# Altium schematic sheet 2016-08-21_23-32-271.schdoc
size 406 x 220 mm; SheetNumber: 1; SheetTotal: 1
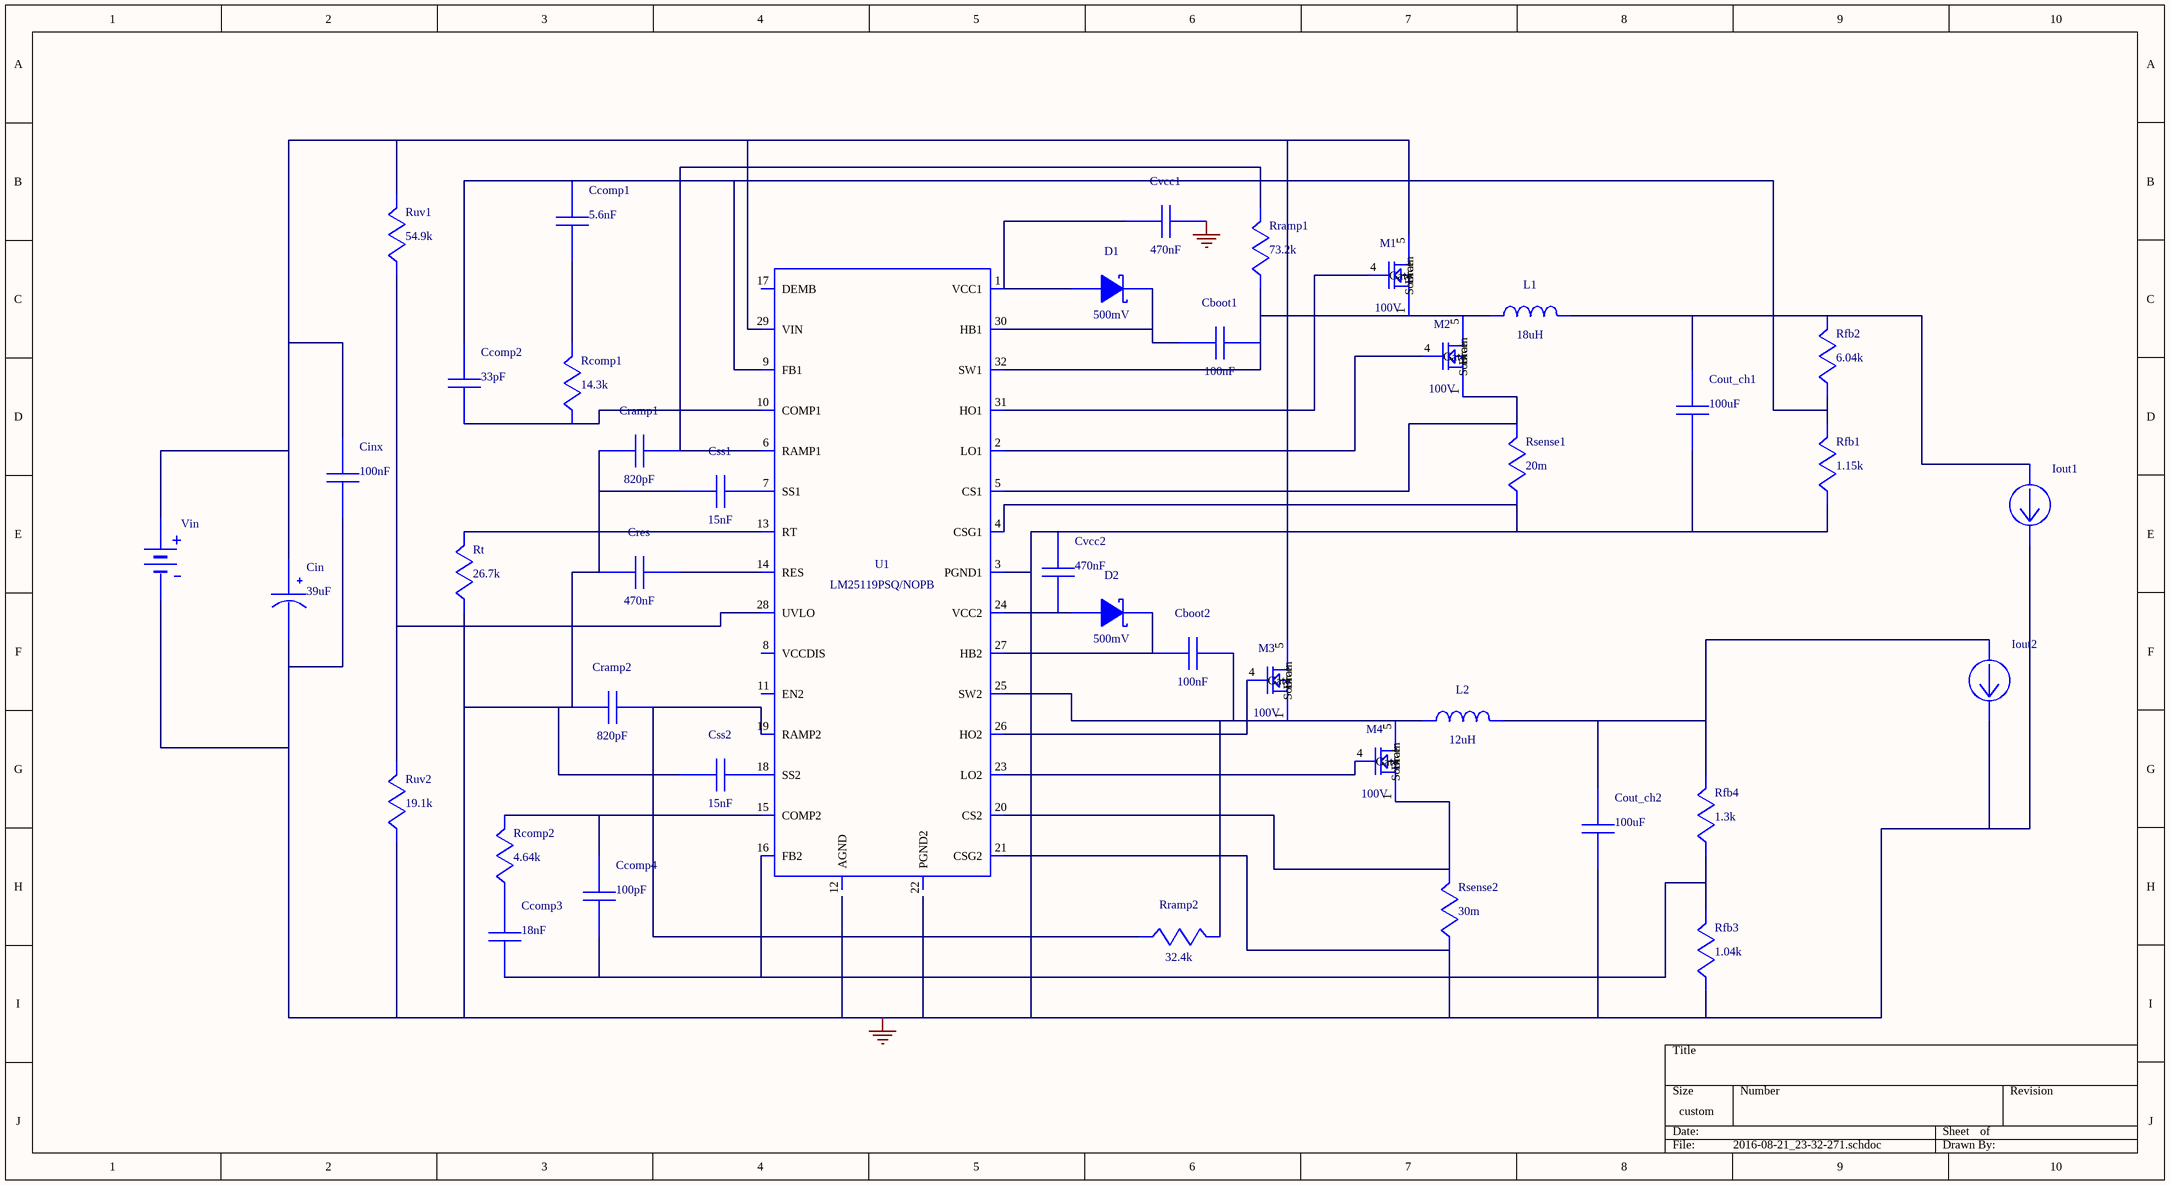
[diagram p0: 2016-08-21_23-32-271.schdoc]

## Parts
Cboot1  value 100nF  (hidden comment: GRM155R61A104KA01D)
Cboot2  value 100nF  (hidden comment: GRM155R61A104KA01D)
Ccomp1  value 5.6nF  (hidden comment: CC0805KRX7R9BB562)
Ccomp2  value 33pF  (hidden comment: C0805C330K5GACTU)
Ccomp3  value 18nF  (hidden comment: CC0805KRX7R9BB183)
Ccomp4  value 100pF  (hidden comment: CC0805JRNPO9BN101)
Cin  value 39uF  (hidden comment: GENERIC_CAP_POLARIZED)
Cinx  value 100nF  (hidden comment: C0805C104K5RACTU)
Cout_ch1  value 100uF  (hidden comment: GRM31CR60J107ME39L)
Cout_ch2  value 100uF  (hidden comment: GRM31CD80G107ME39L)
Cramp1  value 820pF  (hidden comment: CC0805KRX7R9BB821)
Cramp2  value 820pF  (hidden comment: CC0805KRX7R9BB821)
Cres  value 470nF  (hidden comment: GRM155C80J474KE19D)
Css1  value 15nF  (hidden comment: CC0805KRX7R9BB153)
Css2  value 15nF  (hidden comment: CC0805KRX7R9BB153)
Cvcc1  value 470nF  (hidden comment: GRM155R61A474KE15D)
Cvcc2  value 470nF  (hidden comment: GRM155R61A474KE15D)
D1  value 500mV  (hidden comment: SS14-E3/61T)
D2  value 500mV  (hidden comment: SS14-E3/61T)
Iout1  WB_CURRENT_LOAD  (value not drawn)
Iout2  WB_CURRENT_LOAD  (value not drawn)
L1  value 18uH  (hidden comment: SRR1280-180M)
L2  value 12uH  (hidden comment: SRR1206-120ML)
M1  value 100V  (hidden comment: CSD19537Q3)
M2  value 100V  (hidden comment: CSD19537Q3)
M3  value 100V  (hidden comment: CSD19537Q3)
M4  value 100V  (hidden comment: CSD19537Q3)
Rcomp1  value 14.3k  (hidden comment: CRCW040214K3FKED)
Rcomp2  value 4.64k  (hidden comment: CRCW04024K64FKED)
Rfb1  value 1.15k  (hidden comment: CRCW04021K15FKED)
Rfb2  value 6.04k  (hidden comment: CRCW04026K04FKED)
Rfb3  value 1.04k  (hidden comment: RT0805BRD071K04L)
Rfb4  value 1.3k  (hidden comment: CRCW04021K30FKED)
Rramp1  value 73.2k  (hidden comment: CRCW040273K2FKED)
Rramp2  value 32.4k  (hidden comment: CRCW040232K4FKED)
Rsense1  value 20m  (hidden comment: CSR1206FK20L0)
Rsense2  value 30m  (hidden comment: CSR1206FK30L0)
Rt  value 26.7k  (hidden comment: CRCW040226K7FKED)
Ruv1  value 54.9k  (hidden comment: CRCW040254K9FKED)
Ruv2  value 19.1k  (hidden comment: CRCW040219K1FKED)
U1  LM25119PSQ/NOPB
Vin  WB_BATTERY  (value not drawn)

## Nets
0: Cin.2(-) Cinx.2 Cout_ch1.2 Cout_ch2.2 Cramp1.2 Cramp2.2 Cres.2 Css1.2 Css2.2 Cvcc1.2 Cvcc2.2 Iout1.2(-) Iout2.2(-) Rfb1.2 Rfb3.2 Rsense1.2 Rsense2.2 Rt.2 Ruv2.2 U1.3(PGND1) U1.4(CSG1) U1.21(CSG2) U1.33(EP) Vin.2(-)
NetCboot1_1: Cboot1.1 L1.1 M1.1(Source) M1.2(Source) M1.3(Source) M2.5(Drain) M2.6(Drain) M2.7(Drain) M2.8(Drain) M2.9(Drain) Rramp1.2 U1.32(SW1)
NetCboot1_2: Cboot1.2 D1.1(K) U1.30(HB1)
NetCboot2_1: Cboot2.1 L2.1 M3.1(Source) M3.2(Source) M3.3(Source) M4.5(Drain) M4.6(Drain) M4.7(Drain) M4.8(Drain) M4.9(Drain) Rramp2.1 U1.25(SW2)
NetCboot2_2: Cboot2.2 D2.1(K) U1.27(HB2)
NetCcomp1_1: Ccomp1.1 Rcomp1.1
NetCcomp1_2: Ccomp1.2 Ccomp2.2 Rfb1.1 Rfb2.2 U1.9(FB1)
NetCcomp2_1: Ccomp2.1 Rcomp1.2 U1.10(COMP1)
NetCcomp3_1: Ccomp3.1 Rcomp2.2
NetCcomp3_2: Ccomp3.2 Ccomp4.2 Rfb3.1 Rfb4.2 U1.16(FB2)
NetCcomp4_1: Ccomp4.1 Rcomp2.1 U1.15(COMP2)
NetCin_1: Cin.1(+) Cinx.1 M1.5(Drain) M1.6(Drain) M1.7(Drain) M1.8(Drain) M1.9(Drain) M3.5(Drain) M3.6(Drain) M3.7(Drain) M3.8(Drain) M3.9(Drain) Ruv1.1 U1.29(VIN) Vin.1(+)
NetCout_ch1_1: Cout_ch1.1 Iout1.1(+) L1.2 Rfb2.1
NetCout_ch2_1: Cout_ch2.1 Iout2.1(+) L2.2 Rfb4.1
NetCramp1_1: Cramp1.1 Rramp1.1 U1.6(RAMP1)
NetCramp2_1: Cramp2.1 Rramp2.2 U1.19(RAMP2)
NetCres_1: Cres.1 U1.14(RES)
NetCss1_1: Css1.1 U1.7(SS1)
NetCss2_1: Css2.1 U1.18(SS2)
NetCvcc1_1: Cvcc1.1 D1.2(A) U1.1(VCC1)
NetCvcc2_1: Cvcc2.1 D2.2(A) U1.24(VCC2)
NetM1_4: M1.4(Gate) U1.31(HO1)
NetM2_1: M2.1(Source) M2.2(Source) M2.3(Source) Rsense1.1 U1.5(CS1)
NetM2_4: M2.4(Gate) U1.2(LO1)
NetM3_4: M3.4(Gate) U1.26(HO2)
NetM4_1: M4.1(Source) M4.2(Source) M4.3(Source) Rsense2.1 U1.20(CS2)
NetM4_4: M4.4(Gate) U1.23(LO2)
NetRt_1: Rt.1 U1.13(RT)
NetRuv1_2: Ruv1.2 Ruv2.1 U1.28(UVLO)

Not connected (* = marked no-connect by the designer): U1 8(VCCDIS) 11(EN2) 12(AGND) 17(DEMB) 22(PGND2)

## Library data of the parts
Cboot1 Cboot2 = GRM155R61A104KA01D: GRM155R61A104KA0; Manufacturer Name: MuRata
Ccomp1 = CC0805KRX7R9BB562: CC0805KRX7R9BB56; Manufacturer Name: Yageo America
Ccomp2 = C0805C330K5GACTU: Manufacturer Name: Kemet
Ccomp3 = CC0805KRX7R9BB183: CC0805KRX7R9BB18; Manufacturer Name: Yageo America
Ccomp4 = CC0805JRNPO9BN101: CC0805JRNPO9BN10; Manufacturer Name: Yageo America
Cin = GENERIC_CAP_POLARIZED: 50SVPF39M; Manufacturer Name: Panasonic
Cinx = C0805C104K5RACTU: Manufacturer Name: Kemet
Cout_ch1 = GRM31CR60J107ME39L: GRM31CR60J107ME3; Manufacturer Name: MuRata
Cout_ch2 = GRM31CD80G107ME39L: GRM31CD80G107ME3; Manufacturer Name: MuRata
Cramp1 Cramp2 = CC0805KRX7R9BB821: CC0805KRX7R9BB82; Manufacturer Name: Yageo America
Cres = GRM155C80J474KE19D: GRM155C80J474KE1; Manufacturer Name: MuRata
Css1 Css2 = CC0805KRX7R9BB153: CC0805KRX7R9BB15; Manufacturer Name: Yageo America
Cvcc1 Cvcc2 = GRM155R61A474KE15D: GRM155R61A474KE1; Manufacturer Name: MuRata
D1 D2 = SS14-E3/61T: Manufacturer Name: Vishay-Semiconductor
L1 = SRR1280-180M: Manufacturer Name: Bourns
L2 = SRR1206-120ML: Manufacturer Name: Bourns
M1-M4 = CSD19537Q3: Manufacturer Name: Texas Instruments
Rcomp1 = CRCW040214K3FKED: Manufacturer Name: Vishay-Dale
Rcomp2 = CRCW04024K64FKED: Manufacturer Name: Vishay-Dale
Rfb1 = CRCW04021K15FKED: Manufacturer Name: Vishay-Dale
Rfb2 = CRCW04026K04FKED: Manufacturer Name: Vishay-Dale
Rfb3 = RT0805BRD071K04L: Manufacturer Name: Yageo America
Rfb4 = CRCW04021K30FKED: Manufacturer Name: Vishay-Dale
Rramp1 = CRCW040273K2FKED: Manufacturer Name: Vishay-Dale
Rramp2 = CRCW040232K4FKED: Manufacturer Name: Vishay-Dale
Rsense1 = CSR1206FK20L0: Manufacturer Name: Stackpole Electronics Inc
Rsense2 = CSR1206FK30L0: Manufacturer Name: Stackpole Electronics Inc
Rt = CRCW040226K7FKED: Manufacturer Name: Vishay-Dale
Ruv1 = CRCW040254K9FKED: Manufacturer Name: Vishay-Dale
Ruv2 = CRCW040219K1FKED: Manufacturer Name: Vishay-Dale
U1 = LM25119PSQ/NOPB: Manufacturer Name: Texas Instruments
